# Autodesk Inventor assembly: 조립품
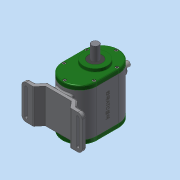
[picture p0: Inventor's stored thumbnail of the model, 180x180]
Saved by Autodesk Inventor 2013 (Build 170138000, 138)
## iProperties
Created: 2018-07
Part Number: 조립품
Document SubType Name: Assembly
Designer: dgall
Mass: 1465.57 g
Surface Area: 2005.9 cm^2
Volume: 679.308 cm^3
Density: 2.15744 g/cm^3
Author: dgall
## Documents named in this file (14)
- C:\Users\dgall\Desktop\380707V1011\조립품.iam
- C:\Users\dgall\Desktop\380707V1011\본체.ipt
- C:\Users\dgall\Desktop\380707V1011\가변스프링.ipt
- C:\Users\dgall\Desktop\380707V1011\뒤커버.ipt
- C:\Users\dgall\Desktop\380707V1011\메인축.ipt
- C:\Users\dgall\Desktop\380707V1011\베어링 608.ipt
- C:\Users\dgall\Desktop\380707V1011\베어링 6003.ipt
- C:\Users\dgall\Desktop\380707V1011\볼트 M4.ipt
- C:\Users\dgall\Desktop\380707V1011\부시.ipt
- C:\Users\dgall\Desktop\380707V1011\서브축.ipt
- C:\Users\dgall\Desktop\380707V1011\슬라이더.ipt
- C:\Users\dgall\Desktop\380707V1011\앞커버.ipt
- C:\Users\dgall\Desktop\380707V1011\오일 실 8 22 7.ipt
- C:\Users\dgall\Desktop\380707V1011\오일 실 17 32 8.ipt
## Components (1 placed, 1 different names)
1. 가변스프링:1
